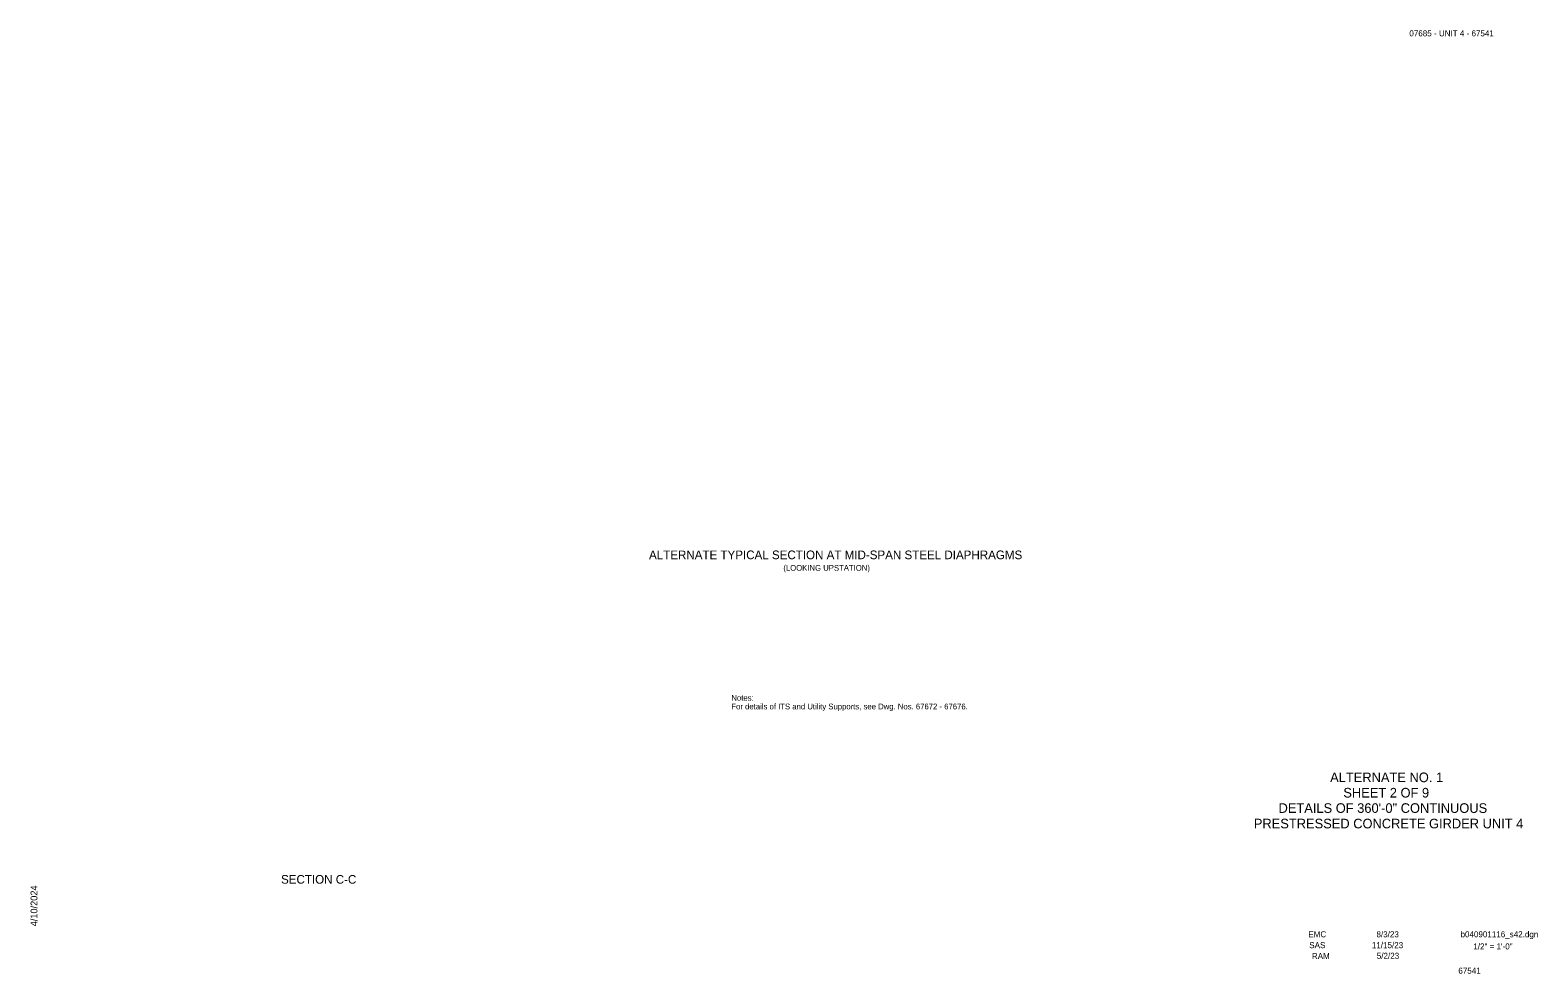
# Model space of a CAD drawing. Extents: x 0.06 to 1.37, y 0.04 to 0.85.
import ezdxf

# ---------------------------------------------------------------- set-up
doc = ezdxf.new("R2010")
doc.units = 0
for name, color, linetype in [('R_ROW', 7, 'Continuous'), ('R_Shade By Others', 7, 'Continuous'), ('R_Survey Control', 7, 'Continuous'), ('R_Wall', 7, 'Continuous')]:
    doc.layers.add(name, color=color, linetype=linetype)

msp = doc.modelspace()

# ---------------------------------------------------------------- texts
at = {"layer": 'R_ROW'}
for s, p in [('ALTERNATE TYPICAL SECTION AT MID-SPAN STEEL DIAPHRAGMS', (0.5958, 0.3964)), ('SECTION C-C', (0.2771, 0.1155))]:
    msp.add_text(s, height=0.0075, dxfattribs=at).set_placement(p)
at = {"layer": 'R_Shade By Others'}
for s, height, p in [('07685 - UNIT 4 - 67541  ', 0.005208, (1.2543, 0.849)), ('ALTERNATE NO. 1', 0.008333, (1.1857, 0.2034)), ('SHEET 2 OF 9', 0.008333, (1.1971, 0.1901)), ('DETAILS OF 360\'-0" CONTINUOUS', 0.008333, (1.141, 0.1768)), ('PRESTRESSED CONCRETE GIRDER UNIT 4', 0.008333, (1.1196, 0.1634)), ('EMC', 0.00521, (1.1668, 0.0691)), ('8/3/23', 0.00521, (1.2258, 0.0691)), ('b040901116_s42.dgn', 0.005208, (1.2986, 0.0691)), ('SAS', 0.00521, (1.1676, 0.0597)), ('RAM', 0.00521, (1.1699, 0.0503)), ('11/15/23', 0.00521, (1.2218, 0.0597)), ('5/2/23', 0.00521, (1.2261, 0.0505)), ('1/2" = 1\'-0"          ', 0.005208, (1.3097, 0.0586)), ('67541  ', 0.00521, (1.2967, 0.0376))]:
    msp.add_text(s, height=height, dxfattribs=at).set_placement(p)
msp.add_text('4/10/2024', height=0.00595, rotation=90, dxfattribs=at).set_placement((0.0661, 0.0786))
at = {"layer": 'R_Survey Control'}
for s, p in [('Notes:', (0.6671, 0.2739)), ('For details of ITS and Utility Supports, see Dwg. Nos. 67672 - 67676.', (0.6671, 0.2664))]:
    msp.add_text(s, height=0.005, dxfattribs=at).set_placement(p)
at = {"layer": 'R_Wall'}
msp.add_text('(LOOKING UPSTATION)', height=0.005, dxfattribs=at).set_placement((0.7121, 0.3864))

doc.saveas('drawing.dxf')
